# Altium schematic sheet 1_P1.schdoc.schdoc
size 459 x 627 mm
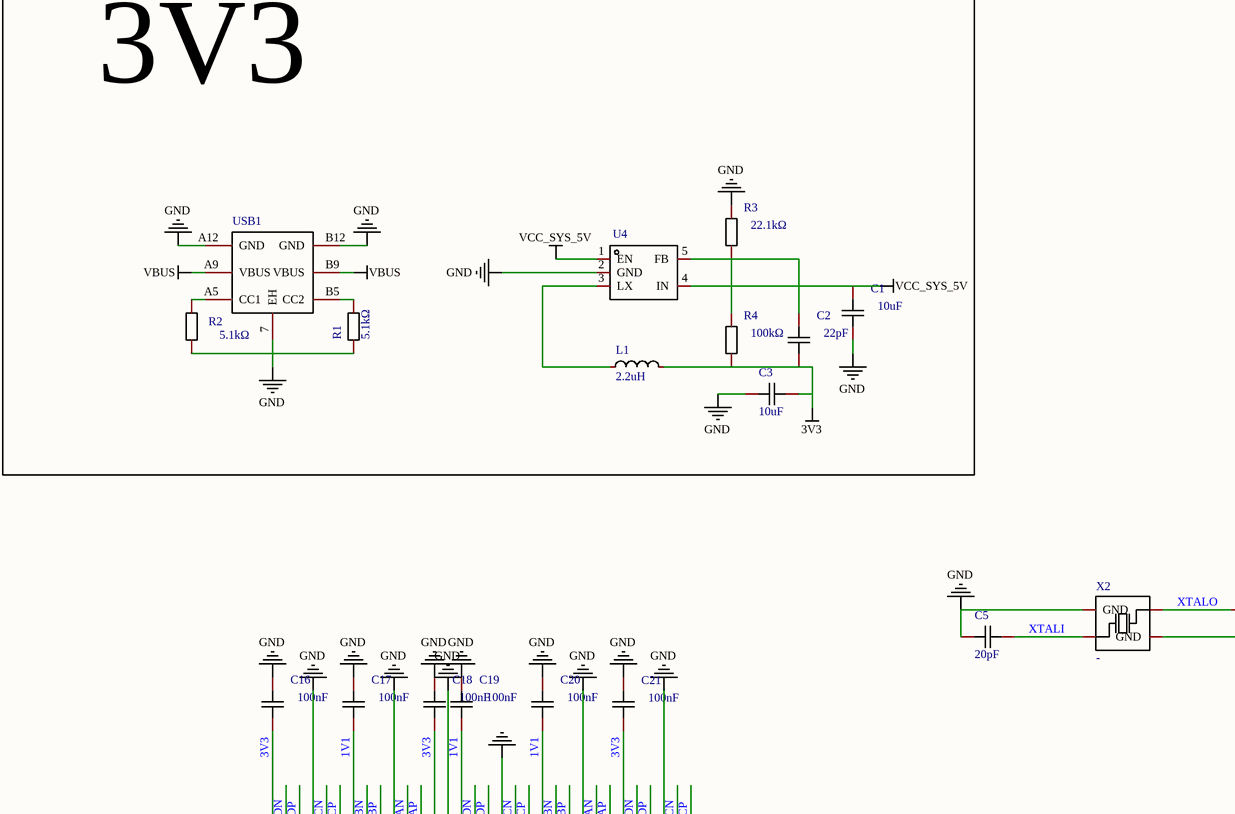
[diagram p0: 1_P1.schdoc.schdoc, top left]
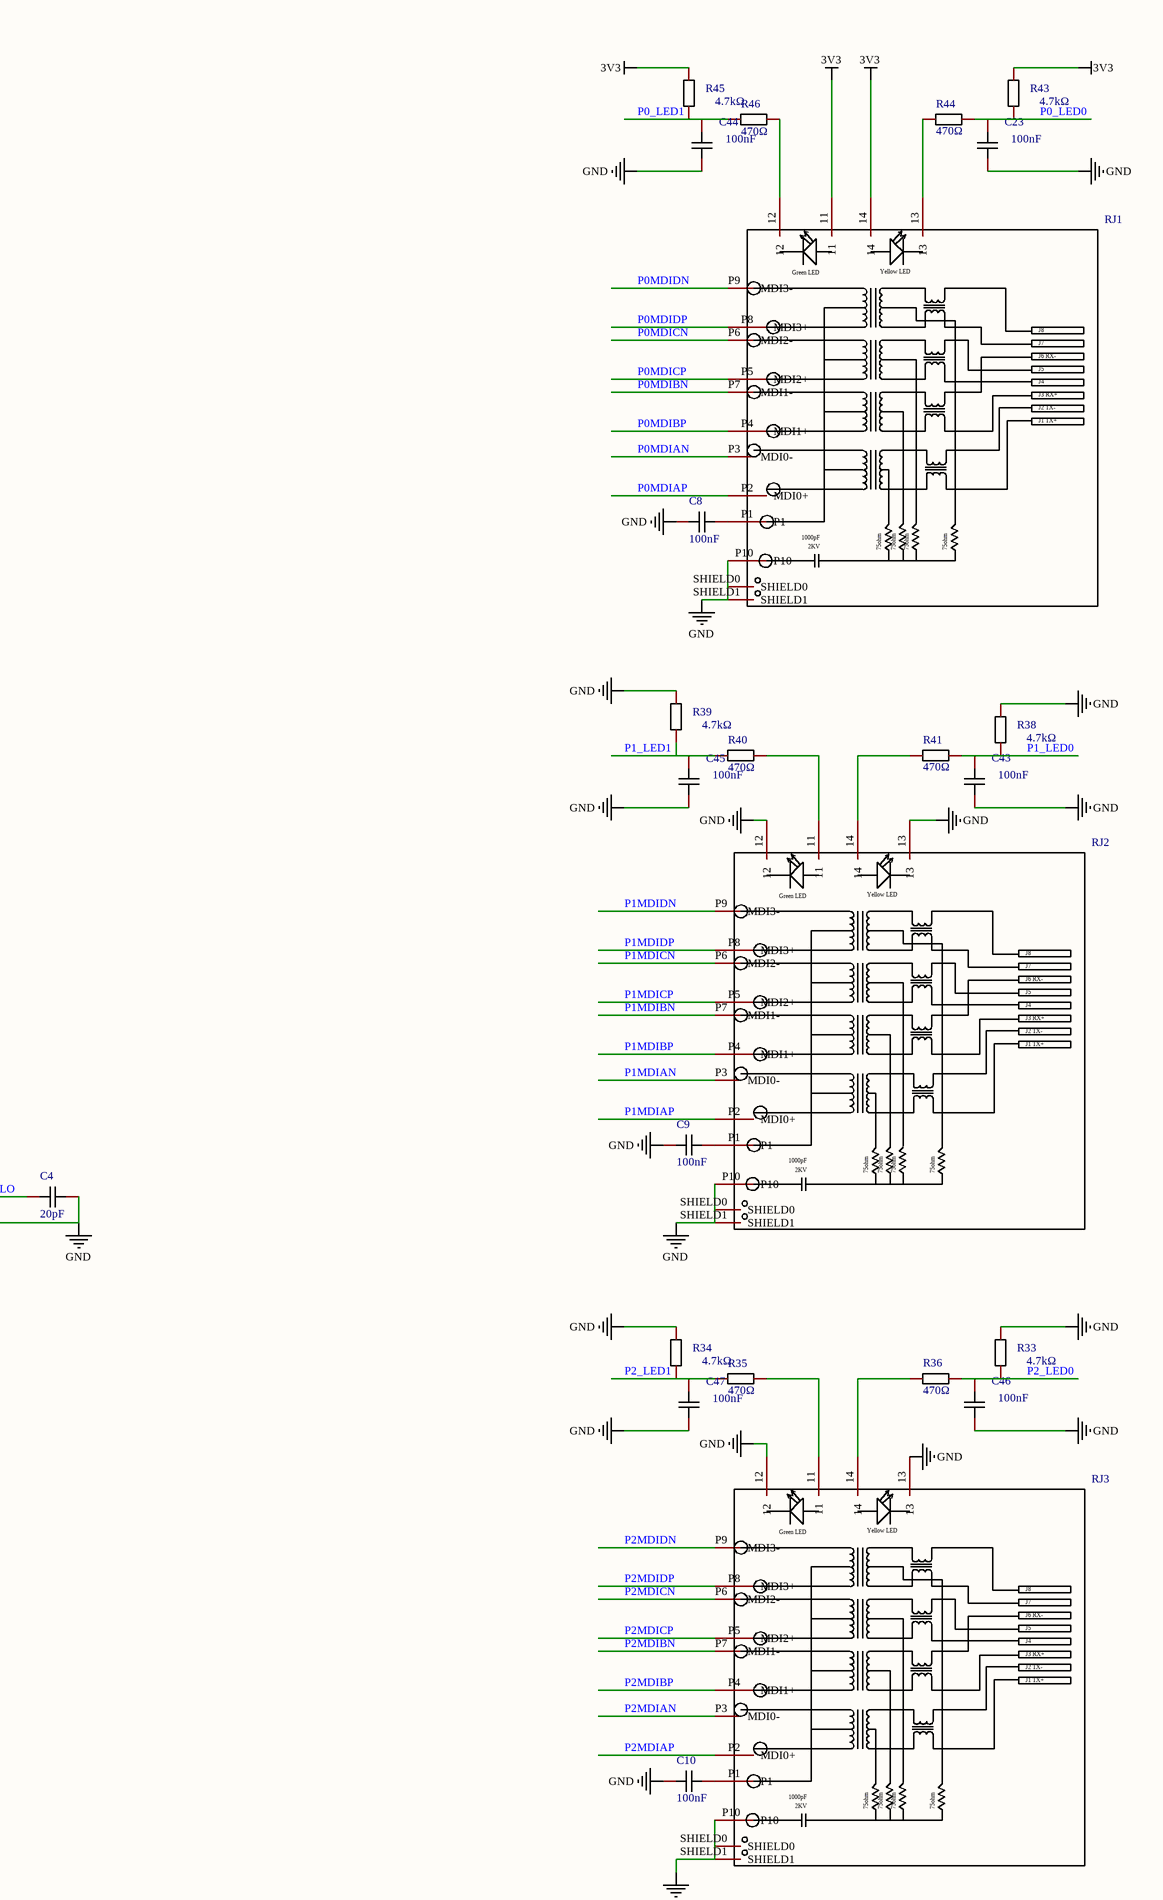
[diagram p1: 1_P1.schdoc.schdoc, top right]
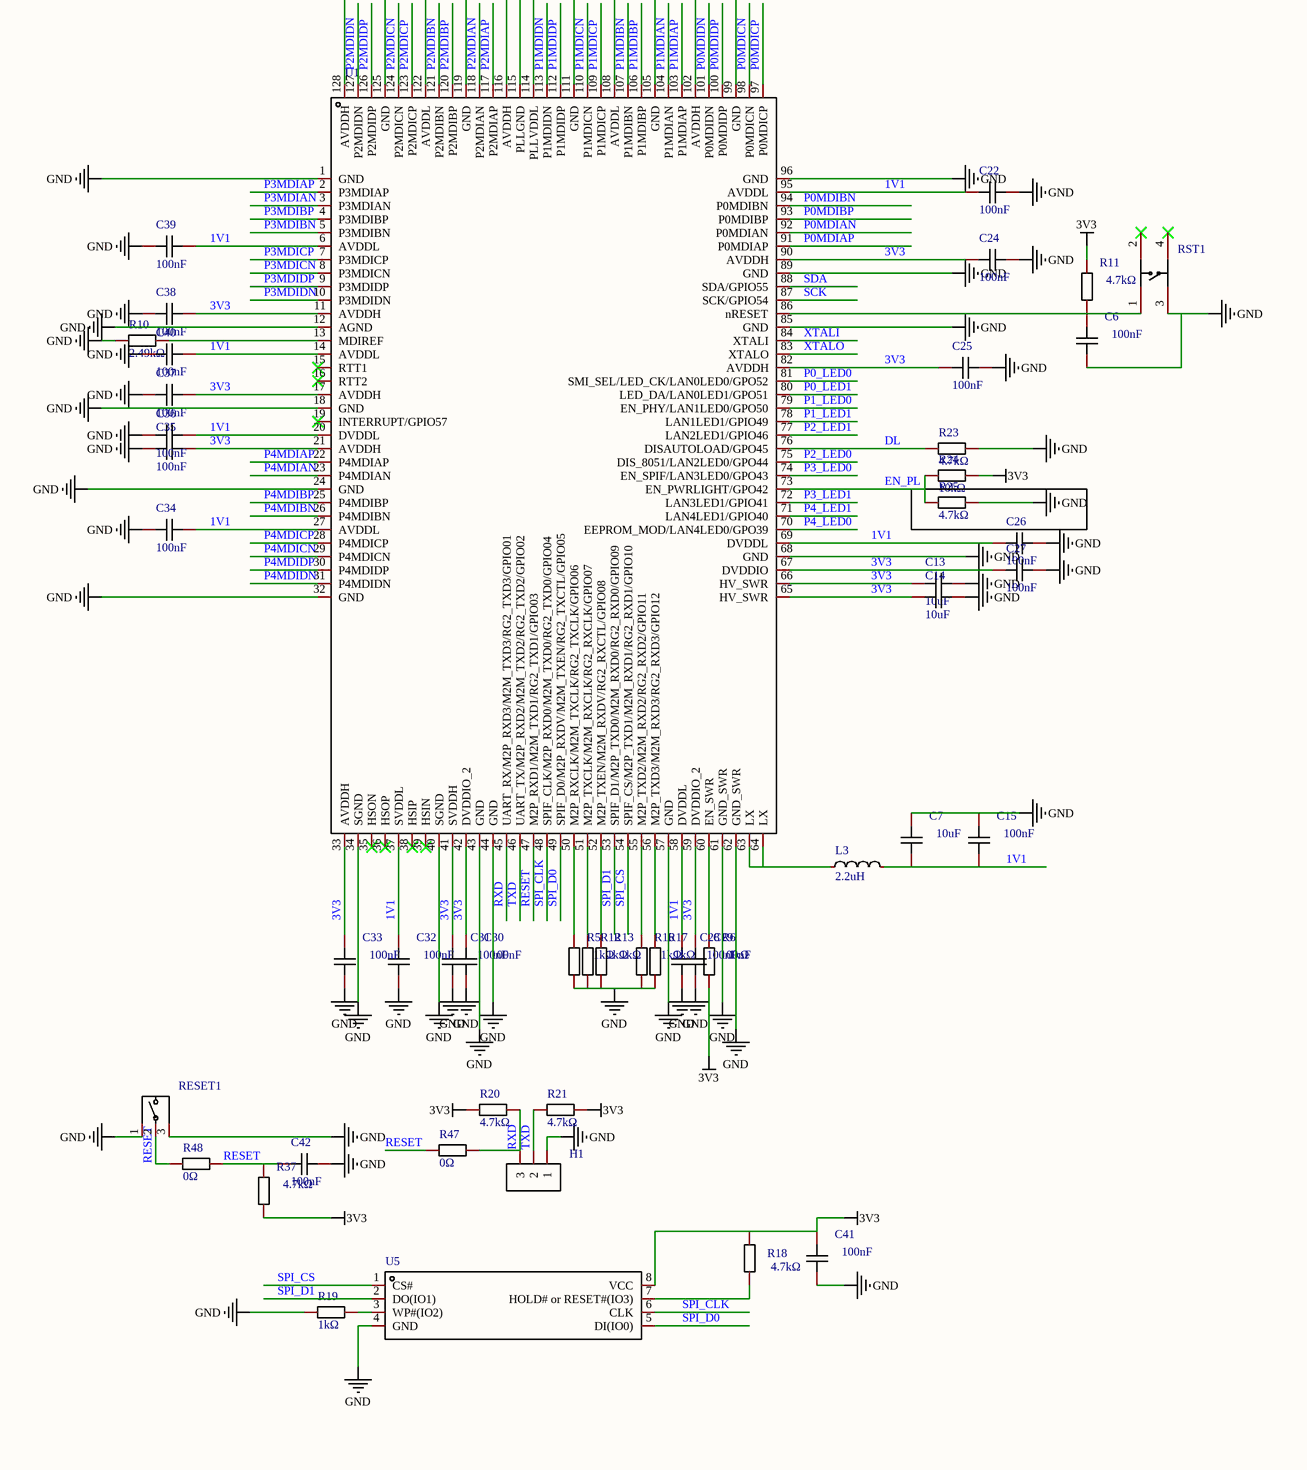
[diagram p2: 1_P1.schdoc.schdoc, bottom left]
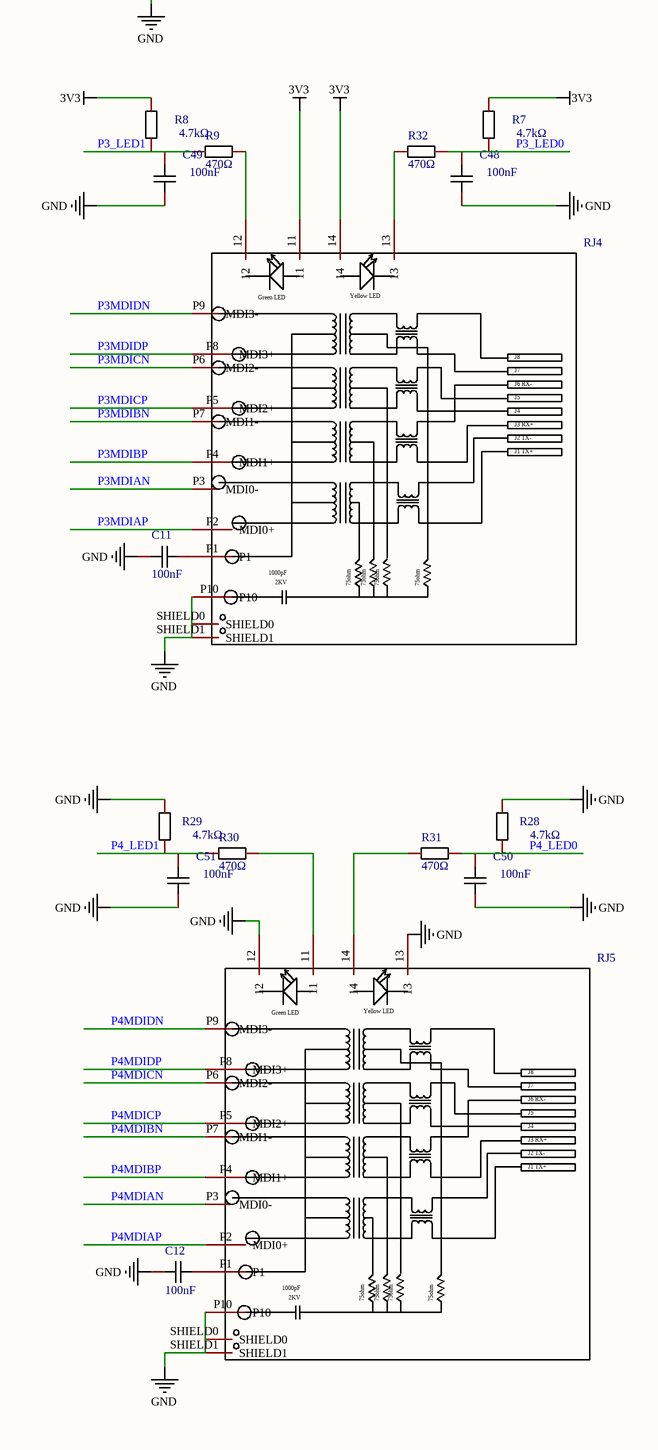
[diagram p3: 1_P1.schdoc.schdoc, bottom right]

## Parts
C1  value 10uF  [c0603]  (hidden comment: cc0603krx7r9bb104)
C2  value 22pF  [c0402]  (hidden comment: fn15x104k250png)
C3  value 10uF  [c0603]  (hidden comment: cc0603krx7r9bb104)
C4  value 20pF  [c0402]  (hidden comment: fn15x104k250png)
C5  value 20pF  [c0402]  (hidden comment: fn15x104k250png)
C6  value 100nF  [c0402]  (hidden comment: fn15x104k250png)
C7  value 10uF  [c0402]  (hidden comment: fn15x104k250png)
C8  value 100nF  [c0402]  (hidden comment: fn15x104k250png)
C9  value 100nF  [c0402]  (hidden comment: fn15x104k250png)
C10  value 100nF  [c0402]  (hidden comment: fn15x104k250png)
C11  value 100nF  [c0402]  (hidden comment: fn15x104k250png)
C12  value 100nF  [c0402]  (hidden comment: fn15x104k250png)
C13  value 10uF  [c0402]  (hidden comment: fn15x104k250png)
C14  value 10uF  [c0402]  (hidden comment: fn15x104k250png)
C15  value 100nF  [c0402]  (hidden comment: fn15x104k250png)
C16  value 100nF  [c0402]  (hidden comment: fn15x104k250png)
C17  value 100nF  [c0402]  (hidden comment: fn15x104k250png)
C18  value 100nF  [c0402]  (hidden comment: fn15x104k250png)
C19  value 100nF  [c0402]  (hidden comment: fn15x104k250png)
C20  value 100nF  [c0402]  (hidden comment: fn15x104k250png)
C21  value 100nF  [c0402]  (hidden comment: fn15x104k250png)
C22  value 100nF  [c0402]  (hidden comment: fn15x104k250png)
C23  value 100nF  [c0402]  (hidden comment: fn15x104k250png)
C24  value 100nF  [c0402]  (hidden comment: fn15x104k250png)
C25  value 100nF  [c0402]  (hidden comment: fn15x104k250png)
C26  value 100nF  [c0402]  (hidden comment: fn15x104k250png)
C27  value 100nF  [c0402]  (hidden comment: fn15x104k250png)
C28  value 100nF  [c0402]  (hidden comment: fn15x104k250png)
C29  value 100nF  [c0402]  (hidden comment: fn15x104k250png)
C30  value 100nF  [c0402]  (hidden comment: fn15x104k250png)
C31  value 100nF  [c0402]  (hidden comment: fn15x104k250png)
C32  value 100nF  [c0402]  (hidden comment: fn15x104k250png)
C33  value 100nF  [c0402]  (hidden comment: fn15x104k250png)
C34  value 100nF  [c0402]  (hidden comment: fn15x104k250png)
C35  value 100nF  [c0402]  (hidden comment: fn15x104k250png)
C36  value 100nF  [c0402]  (hidden comment: fn15x104k250png)
C37  value 100nF  [c0402]  (hidden comment: fn15x104k250png)
C38  value 100nF  [c0402]  (hidden comment: fn15x104k250png)
C39  value 100nF  [c0402]  (hidden comment: fn15x104k250png)
C40  value 100nF  [c0402]  (hidden comment: fn15x104k250png)
C41  value 100nF  [c0402]  (hidden comment: fn15x104k250png)
C42  value 100nF  [c0402]  (hidden comment: fn15x104k250png)
C43  value 100nF  [c0402]  (hidden comment: fn15x104k250png)
C44  value 100nF  [c0402]  (hidden comment: fn15x104k250png)
C45  value 100nF  [c0402]  (hidden comment: fn15x104k250png)
C46  value 100nF  [c0402]  (hidden comment: fn15x104k250png)
C47  value 100nF  [c0402]  (hidden comment: fn15x104k250png)
C48  value 100nF  [c0402]  (hidden comment: fn15x104k250png)
C49  value 100nF  [c0402]  (hidden comment: fn15x104k250png)
C50  value 100nF  [c0402]  (hidden comment: fn15x104k250png)
C51  value 100nF  [c0402]  (hidden comment: fn15x104k250png)
H1  2.54-1*3p针  [hdr-th_3p-p2.54-v-m-1]  (value not drawn)
L1  value 2.2uH  [ind-smd_l2.5-w2.0]  (hidden comment: 252012cdmcdds-2r2mc)
L3  value 2.2uH  [ind-smd_l2.5-w2.0]  (hidden comment: hpi252010-2r2m)
R1  value 5.1kΩ  [r0402]  (hidden comment: tr0402d10k0q1025z)
R2  value 5.1kΩ  [r0402]  (hidden comment: tr0402d10k0q1025z)
R3  value 22.1kΩ  [r0402]  (hidden comment: tr0402d10k0q1025z)
R4  value 100kΩ  [r0402]  (hidden comment: tr0402d10k0q1025z)
R5  value 1kΩ  [r0402]  (hidden comment: tr0402d10k0q1025z)
R6  value 1kΩ  [r0402]  (hidden comment: tr0402d10k0q1025z)
R7  value 4.7kΩ  [r0402]  (hidden comment: tr0402d10k0q1025z)
R8  value 4.7kΩ  [r0402]  (hidden comment: tr0402d10k0q1025z)
R9  value 470Ω  [r0402]  (hidden comment: tr0402d10k0q1025z)
R10  value 2.49kΩ  [r0402]  (hidden comment: tr0402d10k0q1025z)
R11  value 4.7kΩ  [r0402]  (hidden comment: tr0402d10k0q1025z)
R12  value 1kΩ  [r0402]  (hidden comment: tr0402d10k0q1025z)
R13  value 1kΩ  [r0402]  (hidden comment: tr0402d10k0q1025z)
R16  value 1kΩ  [r0402]  (hidden comment: tr0402d10k0q1025z)
R17  value 1kΩ  [r0402]  (hidden comment: tr0402d10k0q1025z)
R18  value 4.7kΩ  [r0402]  (hidden comment: tr0402d10k0q1025z)
R19  value 1kΩ  [r0402]  (hidden comment: tr0402d10k0q1025z)
R20  value 4.7kΩ  [r0402]  (hidden comment: tr0402d10k0q1025z)
R21  value 4.7kΩ  [r0402]  (hidden comment: tr0402d10k0q1025z)
R23  value 4.7kΩ  [r0402]  (hidden comment: tr0402d10k0q1025z)
R24  value 10kΩ  [r0402]  (hidden comment: tr0402d10k0q1025z)
R25  value 4.7kΩ  [r0402]  (hidden comment: tr0402d10k0q1025z)
R28  value 4.7kΩ  [r0402]  (hidden comment: tr0402d10k0q1025z)
R29  value 4.7kΩ  [r0402]  (hidden comment: tr0402d10k0q1025z)
R30  value 470Ω  [r0402]  (hidden comment: tr0402d10k0q1025z)
R31  value 470Ω  [r0402]  (hidden comment: tr0402d10k0q1025z)
R32  value 470Ω  [r0402]  (hidden comment: tr0402d10k0q1025z)
R33  value 4.7kΩ  [r0402]  (hidden comment: tr0402d10k0q1025z)
R34  value 4.7kΩ  [r0402]  (hidden comment: tr0402d10k0q1025z)
R35  value 470Ω  [r0402]  (hidden comment: tr0402d10k0q1025z)
R36  value 470Ω  [r0402]  (hidden comment: tr0402d10k0q1025z)
R37  value 4.7kΩ  [r0402]  (hidden comment: tr0402d10k0q1025z)
R38  value 4.7kΩ  [r0402]  (hidden comment: tr0402d10k0q1025z)
R39  value 4.7kΩ  [r0402]  (hidden comment: tr0402d10k0q1025z)
R40  value 470Ω  [r0402]  (hidden comment: tr0402d10k0q1025z)
R41  value 470Ω  [r0402]  (hidden comment: tr0402d10k0q1025z)
R43  value 4.7kΩ  [r0402]  (hidden comment: tr0402d10k0q1025z)
R44  value 470Ω  [r0402]  (hidden comment: tr0402d10k0q1025z)
R45  value 4.7kΩ  [r0402]  (hidden comment: tr0402d10k0q1025z)
R46  value 470Ω  [r0402]  (hidden comment: tr0402d10k0q1025z)
R47  value 0Ω  [r0402]  (hidden comment: tr0402d10k0q1025z)
R48  value 0Ω  [r0402]  (hidden comment: tr0402d10k0q1025z)
RESET1  st-1133  [key-smd_st-1133]  (value not drawn)
RJ1  hr911130a  [rj45-th_hr911130a]  (value not drawn)
RJ2  hr911130a  [rj45-th_hr911130a]  (value not drawn)
RJ3  hr911130a  [rj45-th_hr911130a]  (value not drawn)
RJ4  hr911130a  [rj45-th_hr911130a]  (value not drawn)
RJ5  hr911130a  [rj45-th_hr911130a]  (value not drawn)
RST1  k2-1808sn-a4sw-01  [key-smd_4p-l4.2-w3.2-p2.20-ls5.1-tl]  (value not drawn)
U1  rtl8367s-cg  [lqfp-128_l14.0-w14.0-p0.40-ls16.0-bl]  (value not drawn)
U4  sy8088iaac  [sot-23-5_l3.0-w1.7-p0.95-ls2.8-bl]  (value not drawn)
U5  w25q32jvssiq  [soic-8_l5.3-w5.3-p1.27-ls8.0-bl]  (value not drawn)
USB1  13  [usb-type-c-th_918-518k2023d5000x]  (value not drawn)
X2  7e25000e20ucg  [crystal-smd_4p-l2.5-w2.0-bl]  (value not drawn)

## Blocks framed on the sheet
3V3: C1-C3 L1 R1-R4 U4 USB1

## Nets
3V3: C2.1 C3.2 C13.1 C14.1 C16.1 C18.1 C21.1 C24.2 C25.1 C27.1 C29.2 C30.2 C31.2 C33.2 C35.2 C37.2 C38.2 C41.2 L1.2 R4.1 R6.1 R7.2 R8.2 R11.2 R18.2 R20.1 R21.2 R24.2 R37.1 R43.2 R45.2 RJ1.11 RJ1.14 RJ4.11 RJ4.14 U1.11(AVDDH) U1.17(AVDDH) U1.21(AVDDH) U1.33(AVDDH) U1.41(SVDDH) U1.42(DVDDIO_2) U1.59(DVDDIO_2) U1.65(HV_SWR) U1.66(HV_SWR) U1.67(DVDDIO) U1.82(AVDDH) U1.90(AVDDH) U1.102(AVDDH) U1.116(AVDDH) U1.128(AVDDH) U5.8(VCC)
GND: C1.1 C3.1 C4.2 C5.1 C6.1 C7.2 C8.1 C9.1 C10.1 C11.1 C12.1 C13.2 C14.2 C15.2 C16.2 C17.2 C18.2 C19.2 C20.2 C21.2 C22.1 C23.1 C24.1 C25.2 C26.2 C27.2 C28.1 C29.1 C30.1 C31.1 C32.1 C33.1 C34.1 C35.1 C36.1 C37.1 C38.1 C39.1 C40.1 C41.1 C42.2 C43.1 C44.1 C45.1 C46.1 C47.1 C48.1 C49.1 C50.1 C51.1 H1.1 R1.1 R2.1 R3.2 R5.1 R10.1 R12.1 R13.1 R16.1 R17.1 R19.1 R23.2 R25.2 R28.2 R29.2 R33.2 R34.2 R38.2 R39.2 RESET1.1 RESET1.3 RJ1.P10 RJ1.SHIELD0 RJ1.SHIELD1 RJ2.12 RJ2.13 RJ2.P10 RJ2.SHIELD0 RJ2.SHIELD1 RJ3.12 RJ3.13 RJ3.P10 RJ3.SHIELD0 RJ3.SHIELD1 RJ4.P10 RJ4.SHIELD0 RJ4.SHIELD1 RJ5.12 RJ5.13 RJ5.P10 RJ5.SHIELD0 RJ5.SHIELD1 RST1.3 U1.1(GND) U1.12(AGND) U1.18(GND) U1.24(GND) U1.32(GND) U1.34(SGND) U1.40(SGND) U1.43(GND) U1.44(GND) U1.57(GND) U1.61(GND_SWR) U1.62(GND_SWR) U1.68(GND) U1.85(GND) U1.89(GND) U1.96(GND) U1.99(GND) U1.105(GND) U1.115(PLLGND) U1.119(GND) U1.125(GND) U4.2(GND) U5.4(GND) USB1.7(EH) USB1.A12(GND) USB1.B12(GND) X2.2(GND) X2.4(GND)
VBUS: USB1.A9(VBUS) USB1.B9(VBUS)
VCC_SYS_5V: C1.2 U4.1(EN) U4.4(IN)
1V1: C7.1 C15.1 C17.1 C19.1 C20.1 C22.2 C26.1 C28.2 C32.2 C34.2 C36.2 C39.2 C40.2 L3.2 U1.6(AVDDL) U1.14(AVDDL) U1.20(DVDDL) U1.27(AVDDL) U1.37(SVDDL) U1.58(DVDDL) U1.69(DVDDL) U1.95(AVDDL) U1.108(AVDDL) U1.114(PLLVDDL) U1.122(AVDDL)
DL: R23.1 U1.76(DISAUTOLOAD/GPO45)
EN_PL: R24.1 R25.1 U1.73(EN_PWRLIGHT/GPO42)
P0_LED0: C23.2 R43.1 R44.2 U1.81(SMI_SEL/LED_CK/LAN0LED0/GPO52)
P0_LED1: C44.2 R45.1 R46.1 U1.80(LED_DA/LAN0LED1/GPO51)
P0MDIAN: RJ1.P3(MDI0-) U1.92(P0MDIAN)
P0MDIAP: RJ1.P2(MDI0+) U1.91(P0MDIAP)
P0MDIBN: RJ1.P7(MDI1-) U1.94(P0MDIBN)
P0MDIBP: RJ1.P4(MDI1+) U1.93(P0MDIBP)
P0MDICN: RJ1.P6(MDI2-) U1.98(P0MDICN)
P0MDICP: RJ1.P5(MDI2+) U1.97(P0MDICP)
P0MDIDN: RJ1.P9(MDI3-) U1.101(P0MDIDN)
P0MDIDP: RJ1.P8(MDI3+) U1.100(P0MDIDP)
P1_LED0: C43.2 R38.1 R41.2 U1.79(EN_PHY/LAN1LED0/GPO50)
P1_LED1: C45.2 R39.1 R40.1 U1.78(LAN1LED1/GPIO49)
P1MDIAN: RJ2.P3(MDI0-) U1.104(P1MDIAN)
P1MDIAP: RJ2.P2(MDI0+) U1.103(P1MDIAP)
P1MDIBN: RJ2.P7(MDI1-) U1.107(P1MDIBN)
P1MDIBP: RJ2.P4(MDI1+) U1.106(P1MDIBP)
P1MDICN: RJ2.P6(MDI2-) U1.110(P1MDICN)
P1MDICP: RJ2.P5(MDI2+) U1.109(P1MDICP)
P1MDIDN: RJ2.P9(MDI3-) U1.113(P1MDIDN)
P1MDIDP: RJ2.P8(MDI3+) U1.112(P1MDIDP)
P2_LED0: C46.2 R33.1 R36.2 U1.75(DIS_8051/LAN2LED0/GPO44)
P2_LED1: C47.2 R34.1 R35.1 U1.77(LAN2LED1/GPIO46)
P2MDIAN: RJ3.P3(MDI0-) U1.118(P2MDIAN)
P2MDIAP: RJ3.P2(MDI0+) U1.117(P2MDIAP)
P2MDIBN: RJ3.P7(MDI1-) U1.121(P2MDIBN)
P2MDIBP: RJ3.P4(MDI1+) U1.120(P2MDIBP)
P2MDICN: RJ3.P6(MDI2-) U1.124(P2MDICN)
P2MDICP: RJ3.P5(MDI2+) U1.123(P2MDICP)
P2MDIDN: RJ3.P9(MDI3-) U1.127(P2MDIDN)
P2MDIDP: RJ3.P8(MDI3+) U1.126(P2MDIDP)
P3_LED0: C48.2 R7.1 R32.2 U1.74(EN_SPIF/LAN3LED0/GPO43)
P3_LED1: C49.2 R8.1 R9.1 U1.72(LAN3LED1/GPIO41)
P3MDIAN: RJ4.P3(MDI0-) U1.3(P3MDIAN)
P3MDIAP: RJ4.P2(MDI0+) U1.2(P3MDIAP)
P3MDIBN: RJ4.P7(MDI1-) U1.5(P3MDIBN)
P3MDIBP: RJ4.P4(MDI1+) U1.4(P3MDIBP)
P3MDICN: RJ4.P6(MDI2-) U1.8(P3MDICN)
P3MDICP: RJ4.P5(MDI2+) U1.7(P3MDICP)
P3MDIDN: RJ4.P9(MDI3-) U1.10(P3MDIDN)
P3MDIDP: RJ4.P8(MDI3+) U1.9(P3MDIDP)
P4_LED0: C50.2 R28.1 R31.2 U1.70(EEPROM_MOD/LAN4LED0/GPO39)
P4_LED1: C51.2 R29.1 R30.1 U1.71(LAN4LED1/GPIO40)
P4MDIAN: RJ5.P3(MDI0-) U1.23(P4MDIAN)
P4MDIAP: RJ5.P2(MDI0+) U1.22(P4MDIAP)
P4MDIBN: RJ5.P7(MDI1-) U1.26(P4MDIBN)
P4MDIBP: RJ5.P4(MDI1+) U1.25(P4MDIBP)
P4MDICN: RJ5.P6(MDI2-) U1.29(P4MDICN)
P4MDICP: RJ5.P5(MDI2+) U1.28(P4MDICP)
P4MDIDN: RJ5.P9(MDI3-) U1.31(P4MDIDN)
P4MDIDP: RJ5.P8(MDI3+) U1.30(P4MDIDP)
RESET: C42.1 R37.2 R47.1 R48.1 R48.2 RESET1.2 U1.47(M2P_RXD1/M2M_TXD1/RG2_TXD1/GPIO03)
RXD: H1.3 R20.2 R47.2 U1.45(UART_RX/M2P_RXD3/M2M_TXD3/RG2_TXD3/GPIO01)
SCK: U1.87(SCK/GPIO54)
SDA: U1.88(SDA/GPIO55)
SPI_CLK: U1.48(SPIF_CLK/M2P_RXD0/M2M_TXD0/RG2_TXD0/GPIO04) U5.6(CLK)
SPI_CS: U1.54(SPIF_CS/M2P_TXD1/M2M_RXD1/RG2_RXD1/GPIO10) U5.1(CS#)
SPI_D0: U1.49(SPIF_D0/M2P_RXDV/M2M_TXEN/RG2_TXCTL/GPIO05) U5.5(DI(IO0))
SPI_D1: U1.53(SPIF_D1/M2P_TXD0/M2M_RXD0/RG2_RXD0/GPIO09) U5.2(DO(IO1))
TXD: H1.2 R21.1 U1.46(UART_TX/M2P_RXD2/M2M_TXD2/RG2_TXD2/GPIO02)
XTALI: C5.2 U1.84(XTALI) X2.1(OSC1)
XTALO: C4.1 U1.83(XTALO) X2.3(OSC2)
NetC2_2: C2.2 R3.1 R4.2 U4.5(FB)
NetC6_2: C6.2 R11.1 RST1.1 U1.86(nRESET)
NetC8_2: C8.2 RJ1.P1
NetC9_2: C9.2 RJ2.P1
NetC10_2: C10.2 RJ3.P1
NetC11_2: C11.2 RJ4.P1
NetC12_2: C12.2 RJ5.P1
NetL1_1: L1.1 U4.3(LX)
NetL3_1: L3.1 U1.63(LX) U1.64(LX)
NetR1_2: R1.2 USB1.B5(CC2)
NetR2_2: R2.2 USB1.A5(CC1)
NetR5_2: R5.2 U1.50(M2P_RXCLK/M2M_TXCLK/RG2_TXCLK/GPIO06)
NetR6_2: R6.2 U1.60(EN_SWR)
NetR9_2: R9.2 RJ4.12
NetR10_2: R10.2 U1.13(MDIREF)
NetR12_2: R12.2 U1.51(M2P_TXCLK/M2M_RXCLK/RG2_RXCLK/GPIO07)
NetR13_2: R13.2 U1.52(M2P_TXEN/M2M_RXDV/RG2_RXCTL/GPIO08)
NetR16_2: R16.2 U1.55(M2P_TXD2/M2M_RXD2/RG2_RXD2/GPIO11)
NetR17_2: R17.2 U1.56(M2P_TXD3/M2M_RXD3/RG2_RXD3/GPIO12)
NetR18_1: R18.1 U5.7(HOLD#_or_RESET#(IO3))
NetR19_2: R19.2 U5.3(WP#(IO2))
NetR30_2: R30.2 RJ5.11
NetR31_1: R31.1 RJ5.14
NetR32_1: R32.1 RJ4.13
NetR35_2: R35.2 RJ3.11
NetR36_1: R36.1 RJ3.14
NetR40_2: R40.2 RJ2.11
NetR41_1: R41.1 RJ2.14
NetR44_1: R44.1 RJ1.13
NetR46_2: R46.2 RJ1.12

Not connected (* = marked no-connect by the designer): RST1 2* 4*; U1 15(RTT1)* 16(RTT2)* 19(INTERRUPT/GPIO57)* 35(HSON)* 36(HSOP)* 38(HSIP)* 39(HSIN)* 111(GND)

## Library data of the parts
C1 C3 = cc0603krx7r9bb104: Manufacturer: YAGEO(国巨); Add into BOM: yes; Tolerance: ±10%; Voltage Rated: 50V; Temperature Coefficient: X7R; Description: 容值:100nF;精度:±10%;额定电压:50V;温度系数:X7R;
C2 C4-C51 = fn15x104k250png: Manufacturer: PSA(信昌电陶); Add into BOM: yes; Tolerance: ±10%; Voltage Rated: 25V; Temperature Coefficient: X7R; Description: 容值:100nF;精度:±10%;额定电压:25V;温度系数:X7R;
H1 = 2.54-1*3p针: Manufacturer: BOOMELE(博穆精密); Symbol: header-male-2.54_1x3; Add into BOM: yes; Pitch: 2.54mm; Description: 间距:2.54mm;总PIN位数:3;排数:1;插针结构:-;行距:-;安装类型:直插;圆针/方针:-;额定电流:-;额定电压:-;配合针长度:-;塑高:-;触头材质:-;触头镀层:-;颜色:黑色;
L1 = 252012cdmcdds-2r2mc: Manufacturer: Sumida(胜美达); Add into BOM: yes; Tolerance: ±20%; Rated Current: 3A; DC Resistance (DCR): 68mΩ; Description: 电感值:2.2uH;精度:±20%;额定电流:3A;直流电阻(DCR):68mΩ;
L3 = hpi252010-2r2m: Manufacturer: 3L COILS(台湾三礼); Add into BOM: yes; Tolerance: ±20%; Rated Current: 1.62A; DC Resistance (DCR): 110mΩ; Description: 电感值:2.2uH;精度:±20%;额定电流:1.62A;直流电阻(DCR):110mΩ;
R1-R13 R16-R21 R23-R25 R28-R41 R43-R48 = tr0402d10k0q1025z: 电阻类型:薄膜电阻;阻值:10kΩ;精度:±0.5%;功率:63mW;温度系数:±25ppm/;最大工作电压:25V;工作温度范围:-55~+155;; Manufacturer: EVER OHMS(天二科技); Symbol: tr0402d10kq1025; Add into BOM: yes; Tolerance: ±0.5%; Power(Watts): 63mW; Temperature Coefficient: ±25ppm/; Overload Voltage (Max): 25V
RESET1 = st-1133: Manufacturer: RISHENG(日昇); Add into BOM: yes; Contact Current: 50mA; Voltage Rating (DC): 12V; Insulation Resistance: 100MΩ; Circuit: 单刀单掷; Actuator Style: 圆形按钮; Actuator/Cap Color: 白色; Operating Force: 180gf@±50gf; Mechanical Life: 100000; Pin Style: SMD接片; Switch Length: 4.5mm; Switch Width: 3.4mm; Description: 触点电流:50mA;额定电压(DC):12V;绝缘电阻:100MΩ;电路结构:单刀单掷;安装方式:卧贴;按钮形状:圆形按钮;按钮/盖帽颜色:白色;作用力:180gf@±50gf;机械寿命:100000;工作温度:-20℃~+85℃;引脚样式:SMD接片;开关长度:4.5mm;开关宽度:3.4mm;
RJ1-RJ5 = hr911130a: Manufacturer: HANRUN(汉仁); Add into BOM: yes; Connector Type: RJ插座; USOC Codes: RJ45; Number of Ports: 1; LED: 有; Description: 连接器类型:RJ插座;USOC代码:RJ45;端口数量:1;等级:-;屏蔽:-;LED:有;
RST1 = k2-1808sn-a4sw-01: 触点电流:50mA;额定电压(DC):12V;绝缘电阻:100MΩ;电路结构:单刀单掷;安装方式:立贴;按钮形状:椭圆形按钮;带灯:-;作用力:250gf@±30gf;机械寿命:100000;工作温度:-25~+85;开关长度:4.2mm;开关宽度:3.25mm;开关高度:2.5mm;; Manufacturer: 韩国韩荣; Add into BOM: yes; Contact Current: 50mA; Voltage Rating (DC): 12V; Insulation Resistance: 100MΩ; Circuit: 单刀单掷; Actuator Style: 椭圆形按钮; Mechanical Life: 100000; Switch Length: 4.2mm; Switch Width: 3.25mm; Switch Height: 2.5mm
U1 = rtl8367s-cg: Manufacturer: REALTEK(瑞昱); Add into BOM: yes; Description: 类型:-;标准:-;接口类型:-;电源电压:-;
U4 = sy8088iaac: Manufacturer: 矽力杰silergy; Add into BOM: yes
U5 = w25q32jvssiq: Manufacturer: WINBOND(华邦); Symbol: w25q32jvssiq_c179173; Add into BOM: yes; Description: 存储器类型:-;存储器构架(格式):-;技术:-;存储器容量:-;时钟频率:-;存储器接口类型:-;
USB1 = 13: 连接器类型:Type-C;标准:USB 2.0;公母:母座;触点数量:6;端口数量:1;安装方式:侧插;额定电流 - 电源:3A;工作温度范围:-30~+85;; Manufacturer: 精拓金; Symbol: 918-518k2023d50000; Add into BOM: yes; Connector Type: Type-C; Gender: 母座; Number of Contacts: 6; Number of Ports: 1; Current Rating - Power (Max): 3A
X2 = 7e25000e20ucg: Manufacturer: SJK(晶科鑫); Add into BOM: yes; Description: 晶振类型:-;频率:-;频率公差:-;频率稳定度:-;负载电容:-;工作温度:-;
